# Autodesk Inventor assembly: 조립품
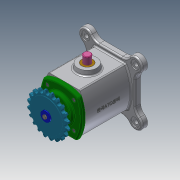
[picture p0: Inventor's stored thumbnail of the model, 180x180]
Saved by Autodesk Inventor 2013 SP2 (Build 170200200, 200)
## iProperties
Created: 2022-01
Part Number: 조립품
Document SubType Name: Assembly
Designer: i
Author: i
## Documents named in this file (13)
- C:\Users\i\Desktop\720106V1026\조립품.iam
- C:\Users\i\Desktop\720106V1026\본체.ipt
- C:\Users\i\Desktop\720106V1026\편심축.ipt
- C:\Users\i\Desktop\720106V1026\커버.ipt
- C:\Users\i\Desktop\720106V1026\베어링 6203.ipt
- C:\Users\i\Desktop\720106V1026\오일 실 17 x 30 x 8.ipt
- C:\Users\i\Desktop\720106V1026\키 5 x 5.ipt
- C:\Users\i\Desktop\720106V1026\스프로킷.ipt
- C:\Users\i\Desktop\720106V1026\부시.ipt
- C:\Users\i\Desktop\720106V1026\슬라이더.ipt
- C:\Users\i\Desktop\720106V1026\볼트 M4 x 12.ipt
- C:\Users\i\Desktop\720106V1026\와셔 4 x 20.ipt
- C:\Users\i\Desktop\720106V1026\육각머리볼트 M4.ipt
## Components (8 placed, 1 different names)
1. M4x0.7x12:1
2. M4x0.7x12:2
3. M4x0.7x12:3
4. M4x0.7x12:4
5. M4x0.7x12:5
6. M4x0.7x12:6
7. M4x0.7x12:7
8. M4x0.7x12:8
